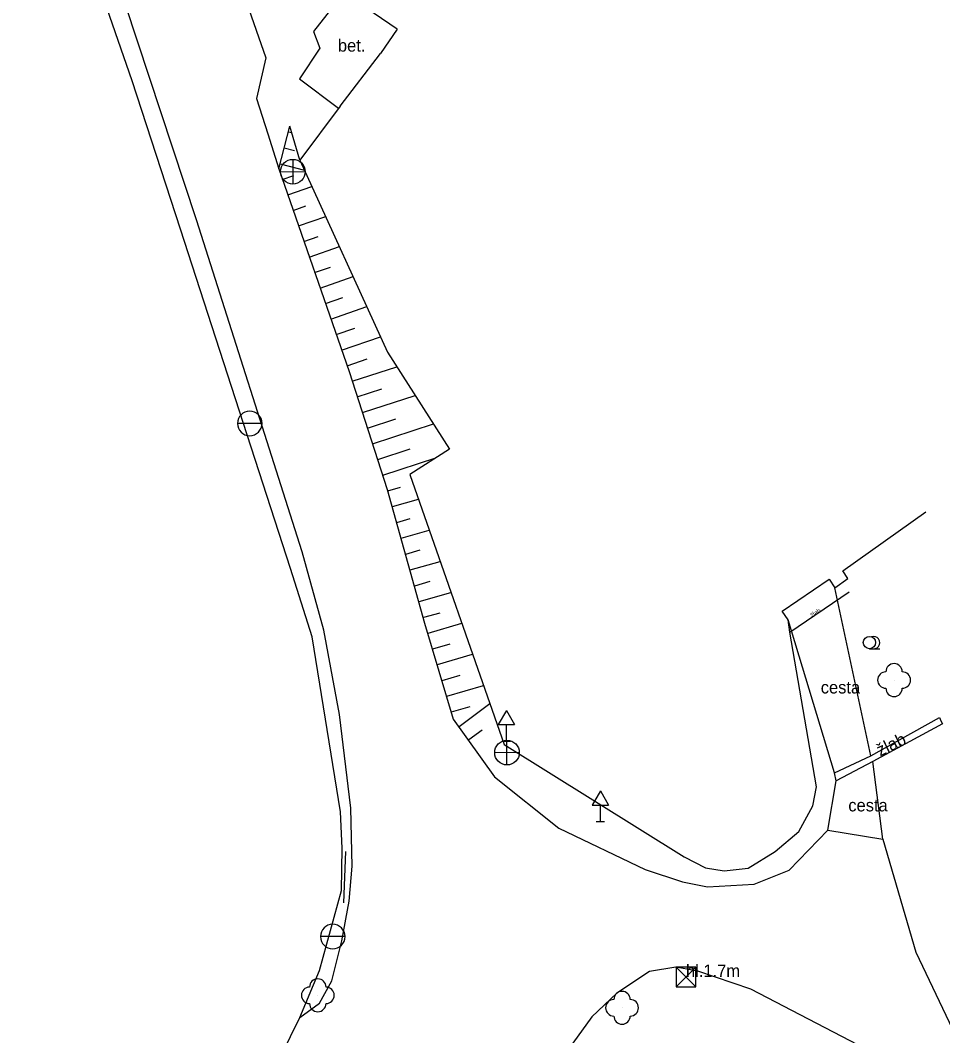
# Model space of a CAD drawing. Extents: x -747135 to -746147, y -1093269 to -1091735.
# Drawn here: x -746621.9 to -746565.8, y -1092924.9 to -1092863.2 of the extents above; entities that cross this region are included whole.
import ezdxf

# ---------------------------------------------------------------- set-up
doc = ezdxf.new("R2010")
doc.units = 0
for name, color, linetype in [('101', 7, 'Continuous'), ('1016', 7, 'Continuous'), ('1029', 7, 'Continuous'), ('105', 7, 'Continuous'), ('23700', 7, 'Continuous'), ('305', 7, 'Continuous'), ('306', 7, 'Continuous'), ('308', 7, 'Continuous'), ('316', 7, 'Continuous'), ('424', 7, 'Continuous'), ('803', 7, 'Continuous')]:
    doc.layers.add(name, color=color, linetype=linetype)

msp = doc.modelspace()

# ---------------------------------------------------------------- linework, layer by layer
at = {"layer": '101'}
for points in [[(-746606.22, -1092872.2), (-746605.54, -1092869.61)], [(-746604.93, -1092871.66), (-746605.54, -1092869.61)], [(-746605.629, -1092869.949), (-746605.449, -1092869.996)], [(-746605.883, -1092870.916), (-746605.252, -1092871.082)], [(-746606.137, -1092871.883), (-746604.65, -1092872.274)], [(-746605.999, -1092872.835), (-746605.306, -1092872.595)], [(-746605.672, -1092873.78), (-746604.196, -1092873.268)], [(-746605.344, -1092874.725), (-746604.561, -1092874.453)], [(-746605.016, -1092875.669), (-746603.361, -1092875.095)], [(-746604.688, -1092876.614), (-746603.816, -1092876.311)], [(-746604.36, -1092877.559), (-746602.526, -1092876.922)], [(-746604.032, -1092878.503), (-746603.07, -1092878.17)], [(-746603.704, -1092879.448), (-746601.691, -1092878.75)], [(-746603.376, -1092880.393), (-746602.325, -1092880.028)], [(-746603.048, -1092881.338), (-746600.857, -1092880.577)], [(-746602.72, -1092882.282), (-746601.58, -1092881.886)], [(-746602.392, -1092883.227), (-746600.022, -1092882.404)], [(-746602.064, -1092884.172), (-746600.835, -1092883.745)], [(-746601.747, -1092885.12), (-746599.026, -1092884.232)], [(-746601.437, -1092886.071), (-746599.953, -1092885.586)], [(-746601.127, -1092887.021), (-746597.912, -1092885.972)], [(-746600.816, -1092887.972), (-746599.086, -1092887.407)], [(-746600.506, -1092888.923), (-746596.798, -1092887.712)], [(-746600.196, -1092889.873), (-746598.218, -1092889.228)], [(-746599.885, -1092890.824), (-746596.655, -1092889.769)], [(-746599.578, -1092891.775), (-746598.816, -1092891.559)], [(-746599.306, -1092892.738), (-746597.722, -1092892.289)], [(-746599.033, -1092893.7), (-746598.213, -1092893.467)], [(-746598.761, -1092894.662), (-746597.061, -1092894.181)], [(-746598.488, -1092895.624), (-746597.609, -1092895.375)], [(-746598.216, -1092896.586), (-746596.4, -1092896.072)], [(-746597.943, -1092897.548), (-746597.006, -1092897.283)], [(-746597.671, -1092898.51), (-746595.739, -1092897.963)], [(-746597.398, -1092899.473), (-746596.403, -1092899.191)], [(-746597.119, -1092900.433), (-746595.085, -1092899.833)], [(-746596.836, -1092901.392), (-746595.795, -1092901.085)], [(-746596.552, -1092902.351), (-746594.425, -1092901.723)], [(-746596.269, -1092903.31), (-746595.182, -1092902.989)], [(-746595.986, -1092904.269), (-746593.764, -1092903.613)], [(-746595.25, -1092906.103), (-746593.376, -1092904.724)], [(-746595.703, -1092905.228), (-746594.568, -1092904.893)], [(-746594.658, -1092906.909), (-746593.844, -1092906.31)]]:
    msp.add_lwpolyline(points, dxfattribs=at)
at = {"layer": '1016'}
for points in [[(-746604.94, -1092923.82), (-746603.73, -1092922.94), (-746602.98, -1092921.58), (-746602.37, -1092919.14), (-746601.93, -1092916.74), (-746601.75, -1092914.6), (-746601.83, -1092911.07), (-746602.53, -1092905.39), (-746603.47, -1092900.25), (-746604.79, -1092895.49), (-746611.22, -1092875.29), (-746616.25, -1092860.06), (-746619.38, -1092851.1), (-746621.94, -1092852.14)], [(-746610.21, -1092860.22), (-746608.17, -1092862.09), (-746607.01, -1092865.45), (-746607.57, -1092867.92), (-746606.89, -1092870.07)], [(-746599.01, -1092863.7), (-746602.25, -1092861.48), (-746604.11, -1092863.85), (-746603.71, -1092864.86), (-746604.95, -1092866.72), (-746602.58, -1092868.51)], [(-746606.89, -1092870.07), (-746606.22, -1092872.2), (-746601.94, -1092884.53), (-746599.63, -1092891.7), (-746597.35, -1092899.83), (-746595.6, -1092905.67), (-746593.1, -1092909.17), (-746589.17, -1092912.29), (-746583.92, -1092914.8), (-746581.66, -1092915.56), (-746580.14, -1092915.86), (-746577.29, -1092915.71), (-746575.17, -1092914.86), (-746572.81, -1092912.41), (-746569.47, -1092912.97), (-746567.46, -1092919.83), (-746565.22, -1092924.53), (-746564.79, -1092924.01)], [(-746570.19, -1092907.9), (-746572.38, -1092897.67)], [(-746572.4, -1092908.93), (-746575.22, -1092899.62)], [(-746572.31, -1092909.42), (-746572.4, -1092908.93), (-746570.19, -1092907.9), (-746566.02, -1092905.57), (-746565.93, -1092905.76), (-746565.84, -1092905.95), (-746570.07, -1092908.25), (-746572.31, -1092909.42)], [(-746569.47, -1092912.97), (-746570.07, -1092908.25)], [(-746572.81, -1092912.41), (-746572.31, -1092909.42)], [(-746567.47, -1092928.76), (-746566.95, -1092927.82), (-746569.47, -1092926.26), (-746577.49, -1092922.09), (-746580.71, -1092921), (-746582.05, -1092920.75), (-746583.67, -1092921.02), (-746585.64, -1092922.33), (-746587.16, -1092923.77), (-746589.64, -1092927.2), (-746592.28, -1092931.27), (-746593.72, -1092934.95), (-746594.32, -1092936.39), (-746593.98, -1092937.68), (-746596.88, -1092942.46), (-746597.95, -1092943.58)]]:
    msp.add_lwpolyline(points, dxfattribs=at)
at = {"layer": '1029'}
msp.add_line((-746570.28, -1092901.385), (-746569.655, -1092901.385), dxfattribs=at)
msp.add_circle((-746570.28, -1092901.01), 0.375, dxfattribs=at)
msp.add_arc((-746570.03, -1092901.01), 0.375, 249.49437, 109.04743, dxfattribs=at)
at = {"layer": '23700'}
msp.add_lwpolyline([(-746575.12, -1092900.37), (-746571.51, -1092897.92)], dxfattribs=at)
at = {"layer": '305'}
for points in [[(-746575.59, -1092899.09), (-746572.73, -1092897.15)], [(-746607.82, -1092929.66), (-746604.94, -1092923.82)]]:
    msp.add_lwpolyline(points, dxfattribs=at)
at = {"layer": '306'}
for p, q in [((-746592.37, -1092905.134), (-746592.87, -1092906)), ((-746592.37, -1092905.134), (-746591.87, -1092906)), ((-746592.87, -1092906), (-746591.87, -1092906)), ((-746592.37, -1092907), (-746592.37, -1092906)), ((-746592.62, -1092907), (-746592.12, -1092907)), ((-746586.65, -1092910.034), (-746587.15, -1092910.9)), ((-746586.65, -1092910.034), (-746586.15, -1092910.9)), ((-746587.15, -1092910.9), (-746586.15, -1092910.9)), ((-746586.65, -1092911.9), (-746586.65, -1092910.9)), ((-746586.9, -1092911.9), (-746586.4, -1092911.9))]:
    msp.add_line(p, q, dxfattribs=at)
at = {"layer": '308'}
for points in [[(-746599.01, -1092863.7), (-746600.03, -1092865.18)], [(-746602.47, -1092868.38), (-746600.03, -1092865.18)], [(-746602.47, -1092868.38), (-746604.93, -1092871.66), (-746599.59, -1092883.35), (-746595.82, -1092889.24)]]:
    msp.add_lwpolyline(points, dxfattribs=at)
at = {"layer": '316'}
for p, q in [((-746605.359, -1092871.622), (-746605.36, -1092873.117)), ((-746606.112, -1092872.364), (-746604.612, -1092872.369)), ((-746607.233, -1092887.68), (-746608.728, -1092887.68)), ((-746592.331, -1092908.448), (-746592.33, -1092906.953)), ((-746591.578, -1092907.706), (-746593.078, -1092907.701)), ((-746602.182, -1092918.89), (-746603.677, -1092918.89)), ((-746582.04, -1092920.74), (-746580.84, -1092921.94)), ((-746580.84, -1092920.74), (-746582.04, -1092921.94)), ((-746580.84, -1092920.74), (-746582.04, -1092920.74)), ((-746582.04, -1092920.74), (-746582.04, -1092921.94)), ((-746580.84, -1092921.94), (-746580.84, -1092920.74)), ((-746582.04, -1092921.94), (-746580.84, -1092921.94))]:
    msp.add_line(p, q, dxfattribs=at)
for centre in [(-746605.36, -1092872.37), (-746592.33, -1092907.7)]:
    msp.add_circle(centre, 0.75, dxfattribs=at)
for centre, start, end in [((-746607.98, -1092887.68), 0, 180), ((-746607.98, -1092887.68), 180, 0), ((-746602.93, -1092918.89), 0, 180), ((-746602.93, -1092918.89), 180, 0)]:
    msp.add_arc(centre, 0.747, start, end, dxfattribs=at)
at = {"layer": '424'}
msp.add_lwpolyline([(-746602.26, -1092916.84), (-746602.13, -1092913.72)], dxfattribs=at)
for centre in [(-746568.78, -1092903.29), (-746603.84, -1092922.46), (-746585.33, -1092923.22)]:
    msp.add_circle(centre, 0.0005, dxfattribs=at)
for centre, start, end in [((-746568.78, -1092902.79), 0, 179.99999), ((-746569.28, -1092903.29), 89.99999, 269.99999), ((-746568.28, -1092903.29), 270, 89.99999), ((-746568.78, -1092903.79), 179.99999, 359.99999), ((-746603.84, -1092921.96), 0, 179.99999), ((-746604.34, -1092922.46), 89.99999, 269.99999), ((-746603.34, -1092922.46), 270, 89.99999), ((-746585.83, -1092923.22), 89.99999, 269.99999), ((-746585.33, -1092922.72), 0, 179.99999), ((-746584.83, -1092923.22), 270, 89.99999), ((-746603.84, -1092922.96), 179.99999, 359.99999), ((-746585.33, -1092923.72), 179.99999, 359.99999)]:
    msp.add_arc(centre, 0.5, start, end, dxfattribs=at)
at = {"layer": '803'}
for points in [[(-746605.5, -1092896.5), (-746612.2, -1092875.87), (-746615.13, -1092866.85), (-746616.83, -1092861.94), (-746619, -1092857.68), (-746621.66, -1092852.93)], [(-746595.82, -1092889.24), (-746598.25, -1092890.78), (-746592.51, -1092907.2), (-746581.55, -1092914.03), (-746580.25, -1092914.71), (-746579.11, -1092914.9), (-746577.65, -1092914.72), (-746576.02, -1092913.72), (-746574.57, -1092912.5), (-746573.72, -1092910.93), (-746573.5, -1092909.78), (-746575.12, -1092900.37), (-746575.22, -1092899.62), (-746575.59, -1092899.09)], [(-746572.73, -1092897.15), (-746572.38, -1092897.67), (-746571.59, -1092897.12), (-746571.9, -1092896.65), (-746566.84, -1092893.06)], [(-746604.94, -1092923.82), (-746603.74, -1092920.95), (-746602.4, -1092916.09), (-746602.36, -1092913.51), (-746602.45, -1092911.31), (-746604.18, -1092900.66), (-746605.5, -1092896.5)]]:
    msp.add_lwpolyline(points, dxfattribs=at)

# ---------------------------------------------------------------- texts
at = {"layer": '105'}
for s, height, rotation, p in [('bet.', 0.75, 0.0053, (-746602.617, -1092865.067)), ('žlab', 0.27, 31.08811, (-746573.791, -1092899.494)), ('cesta', 0.75, 0.0053, (-746573.241, -1092904.105)), ('žlab', 0.75, 25.76502, (-746569.629, -1092907.94)), ('cesta', 0.75, 0.0053, (-746571.565, -1092911.277))]:
    msp.add_text(s, height=height, rotation=rotation, dxfattribs=at).set_placement(p)
msp.add_text('hl.1.7m', height=0.75, dxfattribs=at).set_placement((-746581.44, -1092921.34))

doc.saveas('drawing.dxf')
